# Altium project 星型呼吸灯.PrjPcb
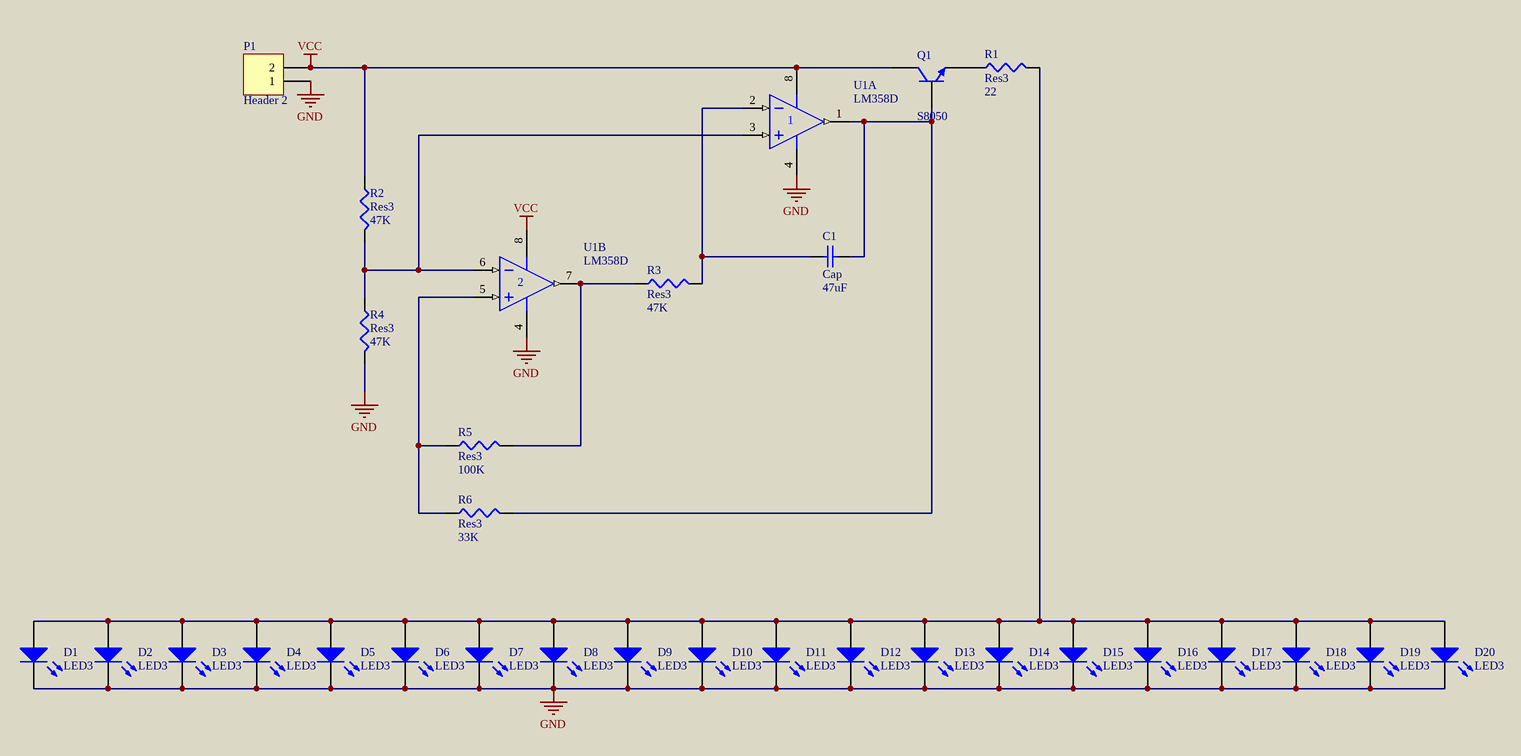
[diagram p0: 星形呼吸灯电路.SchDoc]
1 sheet, 30 parts. Net scope: global (net labels, ports and power ports of the same name join across sheets).

## Sheet 星形呼吸灯电路.SchDoc
size A3

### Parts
C1  Cap  value 47uF  [RAD-0.3]
D1  LED3  [3.5X2.8X1.9]
D2  LED3  [3.5X2.8X1.9]
D3  LED3  [3.5X2.8X1.9]
D4  LED3  [3.5X2.8X1.9]
D5  LED3  [3.5X2.8X1.9]
D6  LED3  [3.5X2.8X1.9]
D7  LED3  [3.5X2.8X1.9]
D8  LED3  [3.5X2.8X1.9]
D9  LED3  [3.5X2.8X1.9]
D10  LED3  [3.5X2.8X1.9]
D11  LED3  [3.5X2.8X1.9]
D12  LED3  [3.5X2.8X1.9]
D13  LED3  [3.5X2.8X1.9]
D14  LED3  [3.5X2.8X1.9]
D15  LED3  [3.5X2.8X1.9]
D16  LED3  [3.5X2.8X1.9]
D17  LED3  [3.5X2.8X1.9]
D18  LED3  [3.5X2.8X1.9]
D19  LED3  [3.5X2.8X1.9]
D20  LED3  [3.5X2.8X1.9]
P1  Header 2  [HDR1X2]
Q1  S8050  [TO-226-AA]
R1  Res3  value 22  [J1-0603]
R2  Res3  value 47K  [J1-0603]
R3  Res3  value 47K  [J1-0603]
R4  Res3  value 47K  [J1-0603]
R5  Res3  value 100K  [J1-0603]
R6  Res3  value 33K  [J1-0603]
U1  LM358D  [751-02]  (parts A,B of 2)

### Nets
GND: D1.2(K) D2.2(K) D3.2(K) D4.2(K) D5.2(K) D6.2(K) D7.2(K) D8.2(K) D9.2(K) D10.2(K) D11.2(K) D12.2(K) D13.2(K) D14.2(K) D15.2(K) D16.2(K) D17.2(K) D18.2(K) D19.2(K) D20.2(K) P1.1 R4.2 U1.4(V-)
VCC: P1.2 Q1.1(C) R2.1 U1.8(V+)
NetC1_1: C1.1 R3.2 U1.2(IN-)
NetC1_2: C1.2 Q1.2(B) R6.2 U1.1(OUT)
NetD1_1: D1.1(A) D2.1(A) D3.1(A) D4.1(A) D5.1(A) D6.1(A) D7.1(A) D8.1(A) D9.1(A) D10.1(A) D11.1(A) D12.1(A) D13.1(A) D14.1(A) D15.1(A) D16.1(A) D17.1(A) D18.1(A) D19.1(A) D20.1(A) R1.2
NetQ1_3: Q1.3(E) R1.1
NetR2_2: R2.2 R4.1 U1.3(IN+) U1.6(IN-)
NetR3_1: R3.1 R5.2 U1.7(OUT)
NetR5_1: R5.1 R6.1 U1.5(IN+)

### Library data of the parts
C1 = Cap: Capacitor
D1-D20 = LED3: Typical BLUE SiC LED
P1 = Header 2: Header, 2-Pin
Q1 = NPN: NPN Bipolar Transistor
R1-R6 = Res3: Resistor
U1 = LM358D: Dual Low-Power Operational Amplifier; Code - JEDEC: MS-012-AA; Code - IPC: SO8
